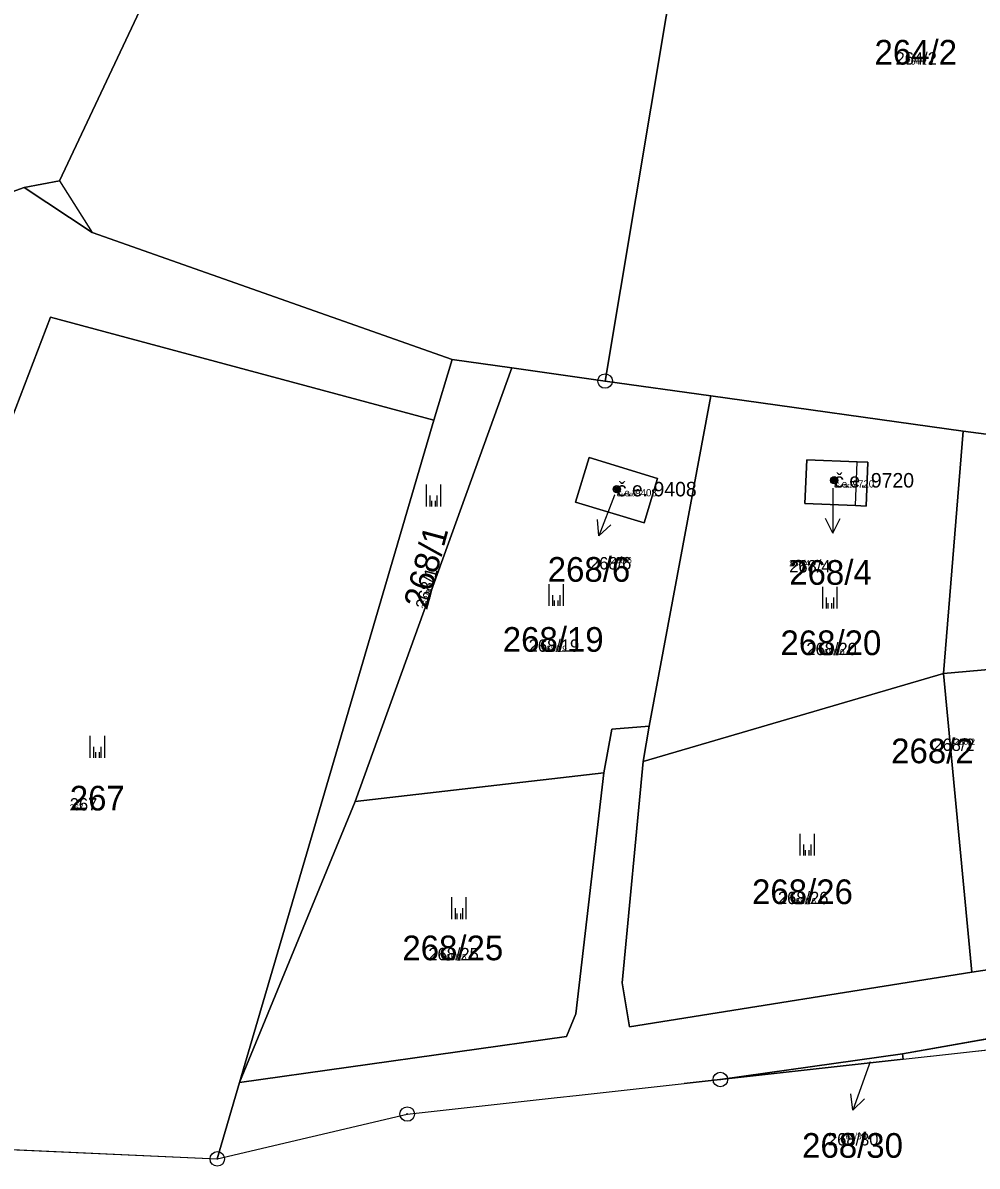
# Model space of a CAD drawing. Extents: x -759873 to -758487, y -975024 to -973516.
# Drawn here: x -758821 to -758755.3, y -974802.3 to -974723.5 of the extents above; entities that cross this region are included whole.
import ezdxf

# ---------------------------------------------------------------- set-up
doc = ezdxf.new("R2010")
doc.units = 0
for name, color, linetype in [('KAT_01_hranice KU', 7, 'Continuous'), ('KAT_02_hranice parcel', 7, 'Continuous'), ('KAT_03_1000_st čísla parcelní', 7, 'Continuous'), ('KAT_03_1000_čísla parcelní', 7, 'Continuous'), ('KAT_03_1000_čísla popisná', 7, 'Continuous'), ('KAT_03_250_st čísla parcelní', 7, 'Continuous'), ('KAT_03_250_čísla parcelní', 7, 'Continuous'), ('KAT_03_250_čísla popisná', 7, 'Continuous'), ('KAT_03_500_st čísla parcelní', 7, 'Continuous'), ('KAT_03_500_čísla parcelní', 7, 'Continuous'), ('KAT_03_500_čísla popisná', 7, 'Continuous'), ('KAT_04_vnitřní kresba', 7, 'Continuous'), ('KAT_05_1000_značky kultur', 7, 'Continuous'), ('KAT_05_250_značky kultur', 7, 'Continuous'), ('KAT_05_500_značky kultur', 7, 'Continuous'), ('KAT_07_1000_značky budov', 7, 'Continuous'), ('KAT_07_250_značky budov', 7, 'Continuous'), ('KAT_07_500_značky budov', 7, 'Continuous'), ('KAT_11_značky bodu BP', 7, 'Continuous'), ('KAT_12_pomocná šipka', 7, 'Continuous'), ('KAT_14_plocha_budovy', 7, 'Continuous'), ('KAT_14_plocha_pozemek', 7, 'Continuous')]:
    doc.layers.add(name, color=color, linetype=linetype)

msp = doc.modelspace()

# ---------------------------------------------------------------- linework, layer by layer
at = {"layer": 'KAT_01_hranice KU'}
msp.add_lwpolyline([(-758837.34, -974800.47), (-758807.64, -974801.81), (-758794.55, -974798.72), (-758784.43, -974797.6), (-758782.7, -974797.41), (-758775.46, -974796.61), (-758772.97, -974796.34), (-758760.37, -974794.94), (-758739.99, -974792.69), (-758721.23, -974790.62), (-758720.5, -974790.48), (-758703.8, -974787.34), (-758681.38, -974776.16), (-758684.15, -974758.2), (-758685.35, -974750.42), (-758685.42, -974707.31), (-758681.69, -974686.2), (-758679.66, -974674.74), (-758630.19, -974674.29), (-758628.19, -974674.27), (-758627.78, -974672.1), (-758618.81, -974624.26)], dxfattribs=at)
at = {"layer": 'KAT_02_hranice parcel'}
for p, q in [((-758780.91, -974748.2), (-758769.32, -974678.97)), ((-758825.18, -974736.38), (-758820.96, -974734.87)), ((-758792.71, -974750.89), (-758791.45, -974746.72)), ((-758787.33, -974747.3), (-758791.45, -974746.72)), ((-758798.13, -974777.18), (-758787.33, -974747.3)), ((-758780.91, -974748.2), (-758787.33, -974747.3)), ((-758773.62, -974749.22), (-758780.91, -974748.2)), ((-758777.88, -974771.98), (-758773.62, -974749.22)), ((-758756.23, -974751.65), (-758773.62, -974749.22)), ((-758806.1, -974796.55), (-758792.71, -974750.89)), ((-758757.58, -974768.36), (-758756.23, -974751.65)), ((-758757.58, -974768.36), (-758737.58, -974766.58)), ((-758778.29, -974774.43), (-758757.58, -974768.36)), ((-758755.63, -974788.94), (-758757.58, -974768.36)), ((-758778.29, -974774.43), (-758777.88, -974771.98)), ((-758798.13, -974777.18), (-758780.99, -974775.2)), ((-758806.1, -974796.55), (-758798.13, -974777.18)), ((-758733.8, -974785.64), (-758755.63, -974788.94)), ((-758760.42, -974794.58), (-758740.22, -974790.99)), ((-758760.37, -974794.94), (-758739.99, -974792.69)), ((-758772.97, -974796.34), (-758760.42, -974794.58)), ((-758760.37, -974794.94), (-758772.97, -974796.34)), ((-758760.42, -974794.58), (-758760.37, -974794.94)), ((-758807.64, -974801.81), (-758806.1, -974796.55)), ((-758772.97, -974796.34), (-758775.46, -974796.61)), ((-758782.7, -974797.41), (-758775.46, -974796.61)), ((-758794.55, -974798.72), (-758784.43, -974797.6)), ((-758784.43, -974797.6), (-758782.7, -974797.41)), ((-758807.64, -974801.81), (-758794.55, -974798.72)), ((-758837.34, -974800.47), (-758807.64, -974801.81))]:
    msp.add_line(p, q, dxfattribs=at)
for points in [[(-758820.96, -974734.87), (-758818.51, -974734.4), (-758801.37, -974698.03), (-758800.04, -974695.13)], [(-758791.45, -974746.72), (-758816.27, -974737.96), (-758820.96, -974734.87)], [(-758848.28, -974787.56), (-758833.49, -974781.3), (-758819.14, -974743.79), (-758792.71, -974750.89)], [(-758750.88, -974746.89), (-758751.31, -974750.65), (-758752, -974752.2), (-758756.23, -974751.65)], [(-758782.02, -974753.48), (-758782.95, -974756.54), (-758778.21, -974757.98), (-758777.29, -974754.92), (-758782.02, -974753.48)], [(-758763.54, -974753.78), (-758767, -974753.64), (-758767.14, -974756.63), (-758763.66, -974756.78), (-758762.91, -974756.83), (-758762.8, -974753.79), (-758763.54, -974753.78)], [(-758777.88, -974771.98), (-758780.44, -974772.2), (-758780.99, -974775.2)], [(-758755.63, -974788.94), (-758779.22, -974792.7), (-758779.74, -974789.67), (-758778.29, -974774.43)], [(-758780.99, -974775.2), (-758782.93, -974791.81), (-758783.58, -974793.38), (-758806.1, -974796.55)]]:
    msp.add_lwpolyline(points, dxfattribs=at)
at = {"layer": 'KAT_03_1000_čísla popisná'}
for centre in [(-758765.12, -974755.04), (-758780.1, -974755.65)]:
    msp.add_circle(centre, 0.25, dxfattribs=at)
at = {"layer": 'KAT_03_250_čísla popisná'}
for centre in [(-758765.12, -974755.04), (-758780.1, -974755.65)]:
    msp.add_circle(centre, 0.0625, dxfattribs=at)
at = {"layer": 'KAT_03_500_čísla popisná'}
for centre in [(-758780.1, -974755.65), (-758765.12, -974755.04)]:
    msp.add_circle(centre, 0.125, dxfattribs=at)
at = {"layer": 'KAT_04_vnitřní kresba'}
for p, q in [((-758818.51, -974734.4), (-758816.27, -974737.96)), ((-758763.66, -974756.78), (-758763.54, -974753.78))]:
    msp.add_line(p, q, dxfattribs=at)
at = {"layer": 'KAT_05_1000_značky kultur'}
for p, q in [((-758793.231, -974756.84), (-758793.231, -974755.34)), ((-758792.23, -974756.84), (-758792.23, -974755.34)), ((-758784.771, -974763.7), (-758784.771, -974762.2)), ((-758783.77, -974763.7), (-758783.77, -974762.2)), ((-758765.911, -974763.88), (-758765.911, -974762.38)), ((-758764.91, -974763.88), (-758764.91, -974762.38)), ((-758816.401, -974774.16), (-758816.401, -974772.66)), ((-758815.4, -974774.16), (-758815.4, -974772.66)), ((-758767.471, -974780.9), (-758767.471, -974779.4)), ((-758766.47, -974780.9), (-758766.47, -974779.4)), ((-758791.481, -974785.28), (-758791.481, -974783.78)), ((-758790.48, -974785.28), (-758790.48, -974783.78))]:
    msp.add_line(p, q, dxfattribs=at)
at = {"layer": 'KAT_05_250_značky kultur'}
for p, q in [((-758792.848, -974756.84), (-758792.848, -974756.465)), ((-758792.598, -974756.84), (-758792.598, -974756.465)), ((-758784.388, -974763.7), (-758784.388, -974763.325)), ((-758784.138, -974763.7), (-758784.138, -974763.325)), ((-758765.528, -974763.88), (-758765.528, -974763.505)), ((-758765.277, -974763.88), (-758765.277, -974763.505)), ((-758816.018, -974774.16), (-758816.018, -974773.785)), ((-758815.767, -974774.16), (-758815.767, -974773.785)), ((-758767.088, -974780.9), (-758767.088, -974780.525)), ((-758766.838, -974780.9), (-758766.838, -974780.525)), ((-758791.098, -974785.28), (-758791.098, -974784.905)), ((-758790.848, -974785.28), (-758790.848, -974784.905))]:
    msp.add_line(p, q, dxfattribs=at)
at = {"layer": 'KAT_05_500_značky kultur'}
for p, q in [((-758792.976, -974756.84), (-758792.976, -974756.09)), ((-758792.475, -974756.84), (-758792.475, -974756.09)), ((-758784.515, -974763.7), (-758784.515, -974762.95)), ((-758784.015, -974763.7), (-758784.015, -974762.95)), ((-758765.655, -974763.88), (-758765.655, -974763.13)), ((-758765.155, -974763.88), (-758765.155, -974763.13)), ((-758816.145, -974774.16), (-758816.145, -974773.41)), ((-758815.645, -974774.16), (-758815.645, -974773.41)), ((-758767.216, -974780.9), (-758767.216, -974780.15)), ((-758766.715, -974780.9), (-758766.715, -974780.15)), ((-758791.226, -974785.28), (-758791.226, -974784.53)), ((-758790.725, -974785.28), (-758790.725, -974784.53))]:
    msp.add_line(p, q, dxfattribs=at)
at = {"layer": 'KAT_07_1000_značky budov'}
for centre in [(-758780.107, -974755.649), (-758765.127, -974755.039)]:
    msp.add_circle(centre, 0.175, dxfattribs=at)
at = {"layer": 'KAT_07_250_značky budov'}
for centre in [(-758765.122, -974755.04), (-758780.102, -974755.65)]:
    msp.add_circle(centre, 0.0437, dxfattribs=at)
at = {"layer": 'KAT_07_500_značky budov'}
for centre in [(-758780.103, -974755.65), (-758765.123, -974755.04)]:
    msp.add_circle(centre, 0.0875, dxfattribs=at)
at = {"layer": 'KAT_11_značky bodu BP'}
for centre, radius in [((-758780.91, -974748.2), 0.5), ((-758780.91, -974748.2), 0.0303), ((-758772.97, -974796.34), 0.5), ((-758772.97, -974796.34), 0.0303), ((-758794.55, -974798.72), 0.5), ((-758794.55, -974798.72), 0.0303), ((-758807.64, -974801.81), 0.5), ((-758807.64, -974801.81), 0.0303)]:
    msp.add_circle(centre, radius, dxfattribs=at)
at = {"layer": 'KAT_12_pomocná šipka'}
for p, q in [((-758780.26, -974756.06), (-758781.335, -974758.862)), ((-758780.25, -974756.04), (-758780.26, -974756.06)), ((-758765.21, -974755.58), (-758765.21, -974755.68)), ((-758765.21, -974755.68), (-758765.21, -974758.681)), ((-758781.335, -974758.862), (-758781.444, -974757.747)), ((-758765.21, -974758.681), (-758765.711, -974757.68)), ((-758765.21, -974758.681), (-758764.709, -974757.68)), ((-758781.335, -974758.862), (-758780.509, -974758.106)), ((-758762.82, -974795.63), (-758763.846, -974798.45)), ((-758762.64, -974795.12), (-758762.82, -974795.63)), ((-758763.846, -974798.45), (-758763.974, -974797.338)), ((-758763.846, -974798.45), (-758763.033, -974797.68))]:
    msp.add_line(p, q, dxfattribs=at)
at = {"layer": 'KAT_14_plocha_budovy'}
for points in [[(-758782.95, -974756.54), (-758778.21, -974757.98), (-758777.29, -974754.92), (-758782.02, -974753.48)], [(-758767.14, -974756.63), (-758763.66, -974756.78), (-758763.54, -974753.78), (-758767, -974753.64)]]:
    msp.add_lwpolyline(points, close=True, dxfattribs=at)
at = {"layer": 'KAT_14_plocha_pozemek'}
for points in [[(-758743, -974676.78), (-758757.5, -974678.19), (-758769.32, -974678.97), (-758780.91, -974748.2), (-758773.62, -974749.22), (-758756.23, -974751.65), (-758752, -974752.2), (-758751.31, -974750.65), (-758750.88, -974746.89), (-758750.62, -974744.56), (-758749.39, -974733.79), (-758748.41, -974725.03), (-758744.4, -974689.28), (-758744.2, -974687.51), (-758743.77, -974683.44)], [(-758780.91, -974748.2), (-758769.32, -974678.97), (-758772.79, -974679.2), (-758796.23, -974686.87), (-758800.04, -974695.13), (-758801.37, -974698.03), (-758818.51, -974734.4), (-758820.96, -974734.87), (-758816.27, -974737.96), (-758791.45, -974746.72), (-758787.33, -974747.3)], [(-758800.04, -974695.13), (-758801.52, -974695.69), (-758814.06, -974719.44), (-758846.61, -974699.26), (-758855, -974716.35), (-758858.23, -974722.43), (-758831.39, -974738.61), (-758825.18, -974736.38), (-758820.96, -974734.87), (-758818.51, -974734.4), (-758801.37, -974698.03)], [(-758791.45, -974746.72), (-758816.27, -974737.96), (-758820.96, -974734.87), (-758825.18, -974736.38), (-758839.65, -974775.57), (-758848.28, -974787.56), (-758833.49, -974781.3), (-758819.14, -974743.79), (-758792.71, -974750.89)], [(-758807.64, -974801.81), (-758806.1, -974796.55), (-758792.71, -974750.89), (-758819.14, -974743.79), (-758833.49, -974781.3), (-758848.28, -974787.56), (-758837.34, -974800.47)], [(-758787.33, -974747.3), (-758791.45, -974746.72), (-758792.71, -974750.89), (-758806.1, -974796.55), (-758798.13, -974777.18)], [(-758751.31, -974750.65), (-758752, -974752.2), (-758756.23, -974751.65), (-758757.58, -974768.36), (-758737.58, -974766.58), (-758735.9, -974749.49), (-758745.23, -974747.87), (-758750.07, -974747.03), (-758750.88, -974746.89)], [(-758773.62, -974749.22), (-758780.91, -974748.2), (-758787.33, -974747.3), (-758798.13, -974777.18), (-758780.99, -974775.2), (-758780.44, -974772.2), (-758777.88, -974771.98)], [(-758756.23, -974751.65), (-758773.62, -974749.22), (-758777.88, -974771.98), (-758778.29, -974774.43), (-758757.58, -974768.36)], [(-758782.02, -974753.48), (-758782.95, -974756.54), (-758778.21, -974757.98), (-758777.29, -974754.92)], [(-758782.02, -974753.48), (-758777.29, -974754.92), (-758778.21, -974757.98), (-758782.95, -974756.54)], [(-758763.54, -974753.78), (-758767, -974753.64), (-758767.14, -974756.63), (-758763.66, -974756.78), (-758762.91, -974756.83), (-758762.8, -974753.79)], [(-758763.54, -974753.78), (-758762.8, -974753.79), (-758762.91, -974756.83), (-758763.66, -974756.78), (-758767.14, -974756.63), (-758767, -974753.64)], [(-758755.63, -974788.94), (-758733.8, -974785.64), (-758735.2, -974766.38), (-758737.58, -974766.58), (-758757.58, -974768.36)], [(-758757.58, -974768.36), (-758778.29, -974774.43), (-758779.74, -974789.67), (-758779.22, -974792.7), (-758755.63, -974788.94)], [(-758798.13, -974777.18), (-758806.1, -974796.55), (-758783.58, -974793.38), (-758782.93, -974791.81), (-758780.99, -974775.2)], [(-758760.37, -974794.94), (-758739.99, -974792.69), (-758740.22, -974790.99), (-758760.42, -974794.58)], [(-758772.97, -974796.34), (-758760.37, -974794.94), (-758760.42, -974794.58)]]:
    msp.add_lwpolyline(points, close=True, dxfattribs=at)
msp.add_lwpolyline([(-758733.8, -974785.64), (-758755.63, -974788.94), (-758779.22, -974792.7), (-758779.74, -974789.67), (-758778.29, -974774.43), (-758777.88, -974771.98), (-758780.44, -974772.2), (-758780.99, -974775.2), (-758782.93, -974791.81), (-758783.58, -974793.38), (-758806.1, -974796.55), (-758807.64, -974801.81), (-758794.55, -974798.72), (-758784.43, -974797.6), (-758782.7, -974797.41), (-758775.46, -974796.61), (-758772.97, -974796.34), (-758760.42, -974794.58), (-758740.22, -974790.99)], dxfattribs=at)

# ---------------------------------------------------------------- texts
at = {"layer": 'KAT_03_1000_st čísla parcelní'}
for s, p in [('268/6', (-758784.866, -974762.033)), ('268/4', (-758768.22, -974762.243)), ('268/2', (-758761.196, -974774.543))]:
    msp.add_text(s, height=1.7, dxfattribs=at).set_placement(p)
at = {"layer": 'KAT_03_1000_čísla parcelní'}
for s, p in [('264/2', (-758762.343, -974726.39)), ('268/19', (-758787.965, -974766.86)), ('268/20', (-758768.825, -974767.09)), ('267', (-758817.81, -974777.799)), ('268/26', (-758770.785, -974784.25)), ('268/25', (-758794.885, -974788.12)), ('268/30', (-758767.335, -974801.733))]:
    msp.add_text(s, height=1.7, dxfattribs=at).set_placement(p)
msp.add_text('268/1', height=1.7, rotation=75, dxfattribs=at).set_placement((-758793.178, -974763.979))
at = {"layer": 'KAT_03_1000_čísla popisná'}
for s, p in [('č.e. 9720', (-758765.12, -974755.54)), ('č.e. 9408', (-758780.1, -974756.15))]:
    msp.add_text(s, height=1, dxfattribs=at).set_placement(p)
at = {"layer": 'KAT_03_250_st čísla parcelní'}
for s, p in [('268/6', (-758780.491, -974760.758)), ('268/4', (-758768.22, -974760.968)), ('268/2', (-758756.835, -974773.268))]:
    msp.add_text(s, height=0.425, dxfattribs=at).set_placement(p)
at = {"layer": 'KAT_03_250_čísla parcelní'}
for s, p in [('264/2', (-758760.162, -974726.39)), ('268/19', (-758785.281, -974766.86)), ('268/20', (-758766.145, -974767.09)), ('267', (-758817.81, -974777.799)), ('268/26', (-758768.102, -974784.25)), ('268/25', (-758792.197, -974788.12)), ('268/30', (-758764.655, -974800.458))]:
    msp.add_text(s, height=0.425, dxfattribs=at).set_placement(p)
msp.add_text('268/1', height=0.425, rotation=75, dxfattribs=at).set_placement((-758793.178, -974763.979))
at = {"layer": 'KAT_03_250_čísla popisná'}
for s, p in [('č.e. 9720', (-758765.12, -974755.54)), ('č.e. 9408', (-758780.1, -974756.15))]:
    msp.add_text(s, height=0.25, dxfattribs=at).set_placement(p)
at = {"layer": 'KAT_03_500_st čísla parcelní'}
for s, p in [('268/6', (-758781.949, -974761.183)), ('268/4', (-758768.22, -974761.393)), ('268/2', (-758758.288, -974773.693))]:
    msp.add_text(s, height=0.85, dxfattribs=at).set_placement(p)
at = {"layer": 'KAT_03_500_čísla parcelní'}
for s, p in [('264/2', (-758760.889, -974726.39)), ('268/19', (-758786.176, -974766.86)), ('268/20', (-758767.038, -974767.09)), ('267', (-758817.81, -974777.799)), ('268/26', (-758768.997, -974784.25)), ('268/25', (-758793.093, -974788.12)), ('268/30', (-758765.548, -974800.883))]:
    msp.add_text(s, height=0.85, dxfattribs=at).set_placement(p)
msp.add_text('268/1', height=0.85, rotation=75, dxfattribs=at).set_placement((-758793.178, -974763.979))
at = {"layer": 'KAT_03_500_čísla popisná'}
for s, p in [('č.e. 9720', (-758765.12, -974755.54)), ('č.e. 9408', (-758780.1, -974756.15))]:
    msp.add_text(s, height=0.5, dxfattribs=at).set_placement(p)

doc.saveas('drawing.dxf')
